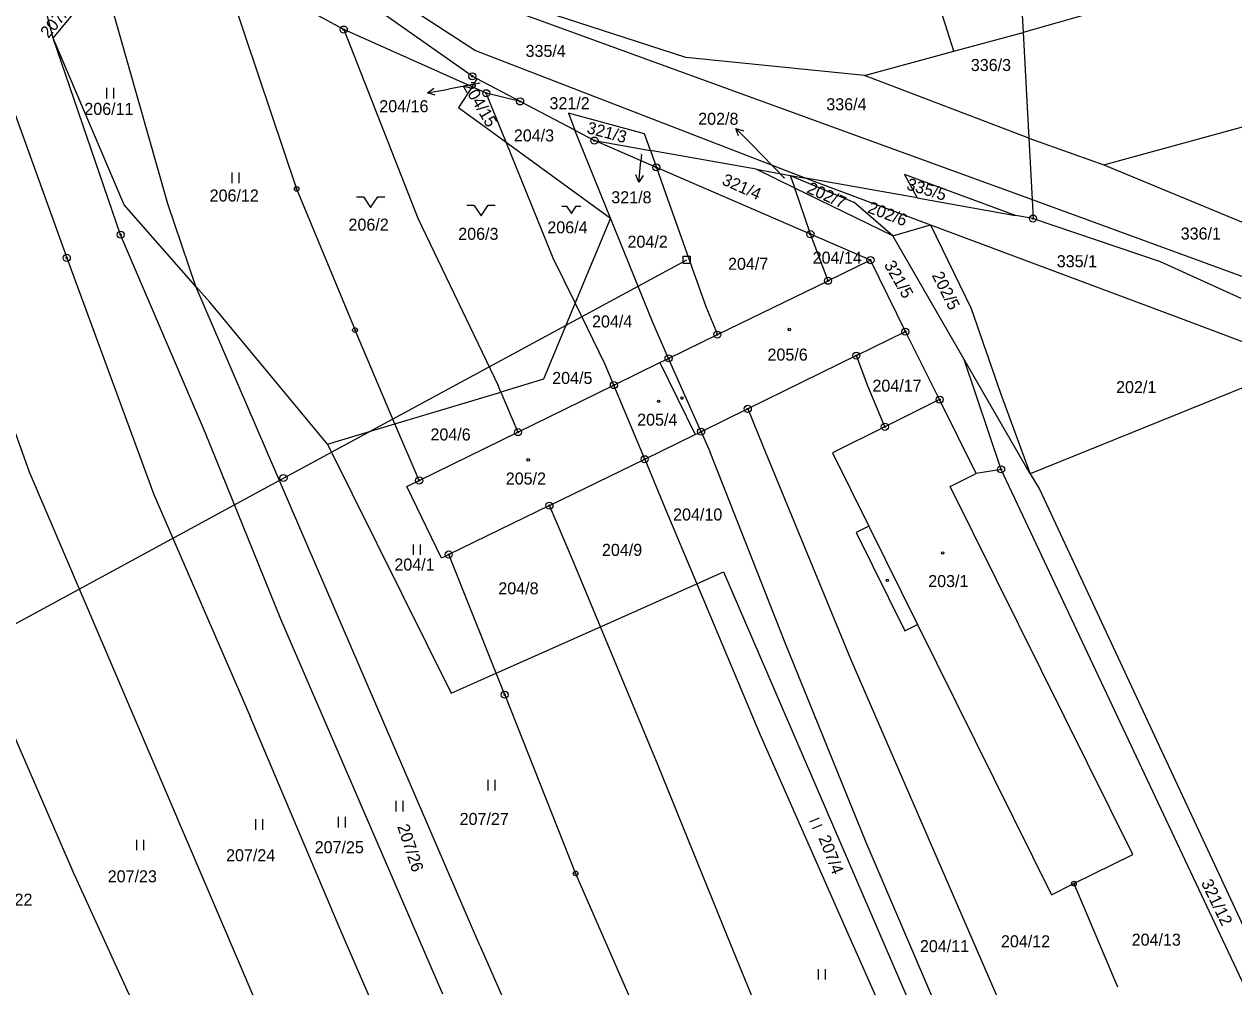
# Model space of a CAD drawing. Extents: x -762263 to -760336, y -1154405 to -1152076.
# Drawn here: x -761293.1 to -761122, y -1152766.2 to -1152630.1 of the extents above; entities that cross this region are included whole.
import ezdxf

# ---------------------------------------------------------------- set-up
doc = ezdxf.new("R2010")
doc.units = 0
for name, color, linetype in [('Vrstva 1', 7, 'Continuous'), ('Vrstva 12', 7, 'Continuous'), ('Vrstva 16', 7, 'Continuous'), ('Vrstva 18', 7, 'Continuous'), ('Vrstva 19', 7, 'Continuous'), ('Vrstva 24', 7, 'Continuous'), ('Vrstva 25', 7, 'Continuous'), ('Vrstva 26', 7, 'Continuous'), ('Vrstva 4', 7, 'Continuous'), ('Vrstva 6', 7, 'Continuous')]:
    doc.layers.add(name, color=color, linetype=linetype)

msp = doc.modelspace()

# ---------------------------------------------------------------- linework, layer by layer
at = {"layer": 'Vrstva 1'}
for p, q in [((-761154.23, -1152586.24), (-761151.83, -1152631.27)), ((-761161.6, -1152633.9), (-761171.9, -1152601.8)), ((-761265.87, -1152610.03), (-761229.28, -1152633.81)), ((-761229.72, -1152637.48), (-761267.05, -1152611.14)), ((-761264.6, -1152623.58), (-761254.56, -1152653.41)), ((-761288.98, -1152632.1), (-761283.69, -1152625.63)), ((-761247.89, -1152630.87), (-761257.04, -1152625.88)), ((-761199.54, -1152634.84), (-761223.07, -1152627.2)), ((-761222.44, -1152628.75), (-761150.56, -1152654.88)), ((-761278.97, -1152655.65), (-761288.98, -1152632.1)), ((-761247.89, -1152630.87), (-761237.42, -1152657.52)), ((-761229.75, -1152638.97), (-761247.89, -1152630.87)), ((-761161.6, -1152633.9), (-761151.83, -1152631.27)), ((-761151.83, -1152631.27), (-761151.03, -1152646.24)), ((-761229.28, -1152633.81), (-761182.55, -1152651.88)), ((-761174.26, -1152637.36), (-761161.6, -1152633.9)), ((-761174.26, -1152637.36), (-761199.54, -1152634.84)), ((-761229.04, -1152637.84), (-761229.72, -1152637.48)), ((-761151.03, -1152646.24), (-761174.26, -1152637.36)), ((-761229.75, -1152638.97), (-761231.68, -1152641.89)), ((-761229.75, -1152638.97), (-761229.04, -1152637.84)), ((-761227.74, -1152639.87), (-761229.75, -1152638.97)), ((-761222.96, -1152641.03), (-761229.04, -1152637.84)), ((-761222.96, -1152641.03), (-761227.74, -1152639.87)), ((-761224.92, -1152646.81), (-761227.74, -1152639.87)), ((-761231.68, -1152641.89), (-761224.92, -1152646.81)), ((-761215.22, -1152645.1), (-761222.96, -1152641.03)), ((-761205.35, -1152645.62), (-761216.1, -1152642.7)), ((-761216.1, -1152642.7), (-761215.22, -1152645.1)), ((-761215.22, -1152645.1), (-761212.44, -1152646.56)), ((-761210.19, -1152657.52), (-761215.22, -1152645.1)), ((-761204.54, -1152647.96), (-761205.35, -1152645.62)), ((-761218.26, -1152663.2), (-761224.92, -1152646.81)), ((-761224.92, -1152646.81), (-761210.19, -1152657.52)), ((-761212.44, -1152646.56), (-761204.54, -1152647.96)), ((-761203.69, -1152650.35), (-761212.44, -1152646.56)), ((-761151.03, -1152646.24), (-761150.56, -1152654.88)), ((-761189.59, -1152650.63), (-761204.54, -1152647.96)), ((-761181.9, -1152659.8), (-761203.69, -1152650.35)), ((-761203.69, -1152650.35), (-761202.4, -1152654)), ((-761184.13, -1152653.28), (-761189.59, -1152650.63)), ((-761189.59, -1152650.63), (-761184.75, -1152651.49)), ((-761184.75, -1152651.49), (-761182.55, -1152651.88)), ((-761166.8, -1152654.68), (-761182.55, -1152651.88)), ((-761182.55, -1152651.88), (-761164.92, -1152658.47)), ((-761152.91, -1152657.15), (-761168.61, -1152651.37)), ((-761168.61, -1152651.37), (-761166.8, -1152654.68)), ((-761254.56, -1152653.41), (-761246.3, -1152673.37)), ((-761202.4, -1152654), (-761196.68, -1152670.04)), ((-761170.25, -1152660.02), (-761184.13, -1152653.28)), ((-761268.8, -1152667.19), (-761278.97, -1152655.65)), ((-761166.8, -1152654.68), (-761152.91, -1152657.15)), ((-761150.56, -1152654.88), (-761150.42, -1152657.59)), ((-761150.56, -1152654.88), (-761087.62, -1152677.96)), ((-761237.42, -1152657.52), (-761226.07, -1152681.21)), ((-761210.19, -1152657.52), (-761215.17, -1152669.5)), ((-761204.21, -1152672.3), (-761210.19, -1152657.52)), ((-761150.42, -1152657.59), (-761152.91, -1152657.15)), ((-761173.41, -1152663.47), (-761181.9, -1152659.8)), ((-761179.41, -1152666.39), (-761181.9, -1152659.8)), ((-761164.92, -1152658.47), (-761128.74, -1152672.01)), ((-761160.15, -1152677.52), (-761170.25, -1152660.02)), ((-761215.17, -1152669.5), (-761218.26, -1152663.2)), ((-761173.41, -1152663.47), (-761179.41, -1152666.39)), ((-761168.48, -1152673.58), (-761173.41, -1152663.47)), ((-761195.06, -1152674), (-761179.41, -1152666.39)), ((-761266.85, -1152669.41), (-761268.8, -1152667.19)), ((-761250.19, -1152689.48), (-761266.85, -1152669.41)), ((-761215.17, -1152669.5), (-761219.67, -1152680.31)), ((-761210.91, -1152678.21), (-761215.17, -1152669.5)), ((-761196.68, -1152670.04), (-761195.06, -1152674)), ((-761240.65, -1152686.61), (-761246.3, -1152673.37)), ((-761201.96, -1152677.36), (-761204.21, -1152672.3)), ((-761128.74, -1152672.01), (-761112.42, -1152678.12)), ((-761201.96, -1152677.36), (-761195.06, -1152674)), ((-761175.41, -1152676.97), (-761168.48, -1152673.58)), ((-761163.63, -1152683.2), (-761168.48, -1152673.58)), ((-761209.69, -1152681.14), (-761210.91, -1152678.21)), ((-761209.69, -1152681.14), (-761203.19, -1152677.96)), ((-761203.19, -1152677.96), (-761201.96, -1152677.36)), ((-761197.36, -1152687.73), (-761201.96, -1152677.36)), ((-761175.41, -1152676.97), (-761190.76, -1152684.5)), ((-761173.83, -1152681.14), (-761175.41, -1152676.97)), ((-761150.81, -1152693.69), (-761160.15, -1152677.52)), ((-761112.42, -1152678.12), (-761150.81, -1152693.69)), ((-761219.67, -1152680.31), (-761225.68, -1152682.12)), ((-761225.68, -1152682.12), (-761226.07, -1152681.21)), ((-761223.26, -1152687.79), (-761209.69, -1152681.14)), ((-761205.34, -1152691.62), (-761209.69, -1152681.14)), ((-761171.38, -1152687.04), (-761173.83, -1152681.14)), ((-761240.65, -1152686.61), (-761225.68, -1152682.12)), ((-761225.68, -1152682.12), (-761223.26, -1152687.79)), ((-761163.63, -1152683.2), (-761171.38, -1152687.04)), ((-761158.46, -1152693.63), (-761163.63, -1152683.2)), ((-761190.76, -1152684.5), (-761197.36, -1152687.73)), ((-761190.76, -1152684.5), (-761188.61, -1152689.74)), ((-761250.19, -1152689.48), (-761240.65, -1152686.61)), ((-761237.23, -1152694.63), (-761240.65, -1152686.61)), ((-761171.38, -1152687.04), (-761178.8, -1152690.72)), ((-761237.23, -1152694.63), (-761223.26, -1152687.79)), ((-761205.34, -1152691.62), (-761198.19, -1152688.14)), ((-761198.19, -1152688.14), (-761197.36, -1152687.73)), ((-761197.36, -1152687.73), (-761196.08, -1152690.62)), ((-761250.19, -1152689.48), (-761232.71, -1152724.72)), ((-761188.61, -1152689.74), (-761176.25, -1152719.87)), ((-761218.81, -1152698.18), (-761205.34, -1152691.62)), ((-761205.34, -1152691.62), (-761202.44, -1152698.58)), ((-761185.49, -1152717.6), (-761196.08, -1152690.62)), ((-761178.8, -1152690.72), (-761173.65, -1152701.1)), ((-761162.14, -1152695.46), (-761158.46, -1152693.63)), ((-761154.94, -1152693.06), (-761158.46, -1152693.63)), ((-761120.45, -1152766.21), (-761154.94, -1152693.06)), ((-761150.81, -1152693.69), (-761149.53, -1152695.84)), ((-761238.97, -1152695.49), (-761237.23, -1152694.63)), ((-761234.07, -1152705.6), (-761238.97, -1152695.49)), ((-761136.32, -1152747.5), (-761162.14, -1152695.46)), ((-761149.53, -1152695.84), (-761118.24, -1152762.89)), ((-761218.81, -1152698.18), (-761233.05, -1152705.1)), ((-761215.55, -1152705.78), (-761218.81, -1152698.18)), ((-761202.44, -1152698.58), (-761197.97, -1152709.24)), ((-761173.65, -1152701.1), (-761175.43, -1152701.98)), ((-761175.43, -1152701.98), (-761168.54, -1152715.9)), ((-761233.05, -1152705.1), (-761234.07, -1152705.6)), ((-761226.34, -1152721.88), (-761233.05, -1152705.1)), ((-761211.59, -1152715.31), (-761215.55, -1152705.78)), ((-761197.97, -1152709.24), (-761194.18, -1152707.55)), ((-761194.18, -1152707.55), (-761166.31, -1152772.15)), ((-761211.59, -1152715.31), (-761197.97, -1152709.24)), ((-761197.97, -1152709.24), (-761189.02, -1152730.61)), ((-761226.34, -1152721.88), (-761211.59, -1152715.31)), ((-761203.45, -1152734.91), (-761211.59, -1152715.31)), ((-761168.54, -1152715.9), (-761166.75, -1152715.01)), ((-761166.75, -1152715.01), (-761147.8, -1152753.21)), ((-761174.02, -1152745.83), (-761185.49, -1152717.6)), ((-761176.25, -1152719.87), (-761135.45, -1152813.8)), ((-761232.71, -1152724.72), (-761226.34, -1152721.88)), ((-761225.13, -1152724.92), (-761226.34, -1152721.88)), ((-761225.13, -1152724.92), (-761215.11, -1152750.19)), ((-761189.02, -1152730.61), (-761176.79, -1152758.28)), ((-761193.62, -1152759.1), (-761203.45, -1152734.91)), ((-761164.38, -1152768.39), (-761174.02, -1152745.83)), ((-761144.64, -1152751.64), (-761136.32, -1152747.5)), ((-761215.11, -1152750.19), (-761179.22, -1152832.52)), ((-761147.8, -1152753.21), (-761144.64, -1152751.64)), ((-761144.64, -1152751.64), (-761138.48, -1152766.24)), ((-761176.79, -1152758.28), (-761164.44, -1152786.14)), ((-761183.54, -1152783.86), (-761193.62, -1152759.1))]:
    msp.add_line(p, q, dxfattribs=at)
at = {"layer": 'Vrstva 12'}
for p, q in [((-761256.42, -1152694.28), (-761199.39, -1152663.43)), ((-761324.27, -1152731.12), (-761256.42, -1152694.28))]:
    msp.add_line(p, q, dxfattribs=at)
at = {"layer": 'Vrstva 16'}
for p, q in [((-761228.64, -1152638.46), (-761233.1, -1152639.28)), ((-761236.05, -1152639.827), (-761233.1, -1152639.28)), ((-761192.431, -1152644.838), (-761190.34, -1152646.99)), ((-761185.59, -1152651.88), (-761190.34, -1152646.99)), ((-761206.164, -1152652.447), (-761205.89, -1152649.46)), ((-761205.8, -1152648.52), (-761205.89, -1152649.46))]:
    msp.add_line(p, q, dxfattribs=at)
for points in [[(-761234.975, -1152640.136), (-761236.05, -1152639.827), (-761235.158, -1152639.153)], [(-761192.092, -1152645.904), (-761192.431, -1152644.838), (-761191.375, -1152645.207)], [(-761205.575, -1152651.497), (-761206.164, -1152652.447), (-761206.571, -1152651.406)]]:
    msp.add_lwpolyline(points, dxfattribs=at)
at = {"layer": 'Vrstva 24'}
for centre, radius in [((-761247.89, -1152630.87), 0.5), ((-761247.89, -1152630.87), 0.1), ((-761229.72, -1152637.48), 0.5), ((-761229.72, -1152637.48), 0.1), ((-761227.74, -1152639.87), 0.5), ((-761227.74, -1152639.87), 0.1), ((-761222.96, -1152641.03), 0.5), ((-761222.96, -1152641.03), 0.1), ((-761212.44, -1152646.56), 0.5), ((-761212.44, -1152646.56), 0.1), ((-761203.69, -1152650.35), 0.5), ((-761203.69, -1152650.35), 0.1), ((-761254.56, -1152653.41), 0.335), ((-761254.56, -1152653.41), 0.067), ((-761150.42, -1152657.59), 0.5), ((-761150.42, -1152657.59), 0.1), ((-761279.45, -1152659.87), 0.5), ((-761279.45, -1152659.87), 0.1), ((-761181.9, -1152659.8), 0.5), ((-761181.9, -1152659.8), 0.1), ((-761287.06, -1152663.15), 0.5), ((-761287.06, -1152663.15), 0.1), ((-761173.41, -1152663.47), 0.5), ((-761173.41, -1152663.47), 0.1), ((-761179.41, -1152666.39), 0.5), ((-761179.41, -1152666.39), 0.1), ((-761246.3, -1152673.37), 0.335), ((-761246.3, -1152673.37), 0.067), ((-761168.48, -1152673.58), 0.5), ((-761168.48, -1152673.58), 0.1), ((-761195.06, -1152674), 0.5), ((-761195.06, -1152674), 0.1), ((-761201.96, -1152677.36), 0.5), ((-761175.41, -1152676.97), 0.5), ((-761175.41, -1152676.97), 0.1), ((-761201.96, -1152677.36), 0.1), ((-761209.69, -1152681.14), 0.5), ((-761209.69, -1152681.14), 0.1), ((-761163.63, -1152683.2), 0.5), ((-761163.63, -1152683.2), 0.1), ((-761190.76, -1152684.5), 0.5), ((-761190.76, -1152684.5), 0.1), ((-761171.38, -1152687.04), 0.5), ((-761171.38, -1152687.04), 0.1), ((-761223.26, -1152687.79), 0.5), ((-761223.26, -1152687.79), 0.1), ((-761197.36, -1152687.73), 0.5), ((-761197.36, -1152687.73), 0.1), ((-761205.34, -1152691.62), 0.5), ((-761205.34, -1152691.62), 0.1), ((-761154.94, -1152693.06), 0.5), ((-761154.94, -1152693.06), 0.1), ((-761237.23, -1152694.63), 0.5), ((-761237.23, -1152694.63), 0.1), ((-761218.81, -1152698.18), 0.5), ((-761218.81, -1152698.18), 0.1), ((-761233.05, -1152705.1), 0.5), ((-761233.05, -1152705.1), 0.1), ((-761225.13, -1152724.92), 0.5), ((-761225.13, -1152724.92), 0.1), ((-761215.11, -1152750.19), 0.335), ((-761215.11, -1152750.19), 0.067), ((-761144.64, -1152751.64), 0.335), ((-761144.64, -1152751.64), 0.067)]:
    msp.add_circle(centre, radius, dxfattribs=at)
at = {"layer": 'Vrstva 25'}
for p, q in [((-761281.42, -1152640.6), (-761281.42, -1152639.1)), ((-761280.42, -1152640.6), (-761280.42, -1152639.1)), ((-761263.67, -1152652.57), (-761263.67, -1152651.07)), ((-761262.67, -1152652.57), (-761262.67, -1152651.07)), ((-761238.05, -1152705.16), (-761238.05, -1152703.66)), ((-761237.05, -1152705.16), (-761237.05, -1152703.66)), ((-761227.48, -1152738.45), (-761227.48, -1152736.95)), ((-761226.48, -1152738.45), (-761226.48, -1152736.95)), ((-761240.49, -1152741.43), (-761240.49, -1152739.93)), ((-761239.49, -1152741.43), (-761239.49, -1152739.93)), ((-761260.35, -1152744.01), (-761260.35, -1152742.51)), ((-761259.35, -1152744.01), (-761259.35, -1152742.51)), ((-761248.66, -1152743.71), (-761248.66, -1152742.21)), ((-761247.66, -1152743.71), (-761247.66, -1152742.21)), ((-761181.995, -1152742.92), (-761180.614, -1152742.335)), ((-761181.605, -1152743.84), (-761180.224, -1152743.255)), ((-761277.15, -1152746.92), (-761277.15, -1152745.42)), ((-761276.15, -1152746.92), (-761276.15, -1152745.42)), ((-761180.75, -1152765.21), (-761180.75, -1152763.71)), ((-761179.75, -1152765.21), (-761179.75, -1152763.71))]:
    msp.add_line(p, q, dxfattribs=at)
for points in [[(-761246.09, -1152654.53), (-761245.09, -1152654.53), (-761244.09, -1152656.03), (-761243.09, -1152654.53), (-761242.09, -1152654.53)], [(-761230.48, -1152655.71), (-761229.48, -1152655.71), (-761228.48, -1152657.21), (-761227.48, -1152655.71), (-761226.48, -1152655.71)], [(-761217.05, -1152655.855), (-761216.38, -1152655.855), (-761215.71, -1152656.86), (-761215.04, -1152655.855), (-761214.37, -1152655.855)]]:
    msp.add_lwpolyline(points, dxfattribs=at)
for centre in [(-761184.89, -1152673.28), (-761203.37, -1152683.44), (-761200.06, -1152682.98), (-761221.81, -1152691.71), (-761163.21, -1152704.87), (-761171.04, -1152708.74)]:
    msp.add_circle(centre, 0.175, dxfattribs=at)
at = {"layer": 'Vrstva 26'}
msp.add_lwpolyline([(-761199.89, -1152662.93), (-761198.89, -1152662.93), (-761198.89, -1152663.93), (-761199.89, -1152663.93)], close=True, dxfattribs=at)
msp.add_circle((-761256.42, -1152694.28), 0.5, dxfattribs=at)
at = {"layer": 'Vrstva 4'}
for p, q in [((-761203.19, -1152677.96), (-761198.19, -1152688.14)), ((-761173.65, -1152701.1), (-761166.75, -1152715.01))]:
    msp.add_line(p, q, dxfattribs=at)
at = {"layer": 'Vrstva 6'}
for p, q in [((-761140.4, -1152649.98), (-761010.32, -1152614.36)), ((-761272.76, -1152655.53), (-761281.36, -1152625.21)), ((-761288.98, -1152632.1), (-761290.35, -1152626.84)), ((-761299.47, -1152628.81), (-761287.06, -1152663.15)), ((-761142.2, -1152628.53), (-761151.83, -1152631.27)), ((-761292.33, -1152693.43), (-761314.49, -1152631.78)), ((-761279.45, -1152659.87), (-761288.98, -1152632.1)), ((-761151.03, -1152646.24), (-761140.4, -1152649.98)), ((-761204.54, -1152647.96), (-761203.69, -1152650.35)), ((-761140.4, -1152649.98), (-761109.42, -1152662.87)), ((-761184.75, -1152651.49), (-761175.75, -1152655.27)), ((-761184.75, -1152651.49), (-761184.13, -1152653.28)), ((-761181.9, -1152659.8), (-761184.13, -1152653.28)), ((-761268.8, -1152667.19), (-761272.76, -1152655.53)), ((-761170.25, -1152660.02), (-761175.75, -1152655.27)), ((-761150.42, -1152657.59), (-761132.45, -1152663.66)), ((-761170.25, -1152660.02), (-761164.92, -1152658.47)), ((-761164.92, -1152658.47), (-761159.19, -1152670.29)), ((-761267.44, -1152687.93), (-761279.45, -1152659.87)), ((-761287.06, -1152663.15), (-761274.73, -1152696.61)), ((-761132.45, -1152663.66), (-761121.06, -1152668.84)), ((-761228.66, -1152760.37), (-761268.8, -1152667.19)), ((-761159.19, -1152670.29), (-761155.04, -1152682.27)), ((-761154.94, -1152693.06), (-761160.15, -1152677.52)), ((-761155.04, -1152682.27), (-761150.81, -1152693.69)), ((-761256.77, -1152714.23), (-761267.44, -1152687.93)), ((-761311.86, -1152690.78), (-761286.2, -1152749.91)), ((-761260.42, -1152768.1), (-761292.33, -1152693.43)), ((-761274.73, -1152696.61), (-761261.14, -1152728.02)), ((-761233.9, -1152767.28), (-761256.77, -1152714.23)), ((-761248.31, -1152758.32), (-761261.14, -1152728.02)), ((-761286.2, -1152749.91), (-761252.11, -1152824.66)), ((-761228.79, -1152802.98), (-761248.31, -1152758.32)), ((-761228.66, -1152760.37), (-761200.52, -1152824.24))]:
    msp.add_line(p, q, dxfattribs=at)

# ---------------------------------------------------------------- texts
at = {"layer": 'Vrstva 16'}
for s, p in [('204/16', (-761242.868, -1152642.55)), ('202/8', (-761197.773, -1152644.33)), ('321/8', (-761210.06, -1152655.43))]:
    msp.add_text(s, height=1.7, dxfattribs=at).set_placement(p)
at = {"layer": 'Vrstva 18'}
for s, rotation, p in [('207/28', 50.1911, (-761289.658, -1152632.195)), ('204/15', 300.63096, (-761231.108, -1152638.856)), ('321/3', 345.26437, (-761213.64, -1152645.49)), ('321/4', 336.15434, (-761194.549, -1152652.718)), ('202/7', 335.75327, (-761182.532, -1152653.885)), ('335/5', 343.08713, (-761168.421, -1152653.443)), ('202/6', 339.13372, (-761173.941, -1152656.695)), ('321/5', 299.82881, (-761171.548, -1152664.124)), ('202/5', 296.84943, (-761164.76, -1152665.61)), ('207/26', 288.42695, (-761240.355, -1152743.542)), ('207/4', 291.34904, (-761180.802, -1152745.176)), ('321/12', 295.87541, (-761126.708, -1152751.506))]:
    msp.add_text(s, height=1.7, rotation=rotation, dxfattribs=at).set_placement(p)
for s, height, p in [('335/4', 1.7, (-761222.183, -1152634.74)), ('336/3', 1.7, (-761159.223, -1152636.73)), ('204/16', 0.1, (-761228.868, -1152638.46)), ('321/2', 1.7, (-761218.803, -1152642.13)), ('336/4', 1.7, (-761179.653, -1152642.28)), ('206/11', 1.7, (-761284.577, -1152642.93)), ('204/3', 1.7, (-761223.841, -1152646.69)), ('321/8', 0.1, (-761205.992, -1152648.52)), ('202/8', 0.1, (-761185.803, -1152651.88)), ('206/12', 1.7, (-761266.858, -1152655.18)), ('206/2', 1.7, (-761247.223, -1152659.3)), ('206/4', 1.7, (-761219.104, -1152659.68)), ('206/3', 1.7, (-761231.703, -1152660.6)), ('336/1', 1.7, (-761129.539, -1152660.56)), ('204/2', 1.7, (-761207.767, -1152661.71)), ('204/7', 1.7, (-761193.553, -1152664.84)), ('204/14', 1.7, (-761181.585, -1152663.97)), ('335/1', 1.7, (-761147.066, -1152664.47)), ('204/4', 1.7, (-761212.784, -1152672.99)), ('204/5', 1.7, (-761218.42, -1152680.98)), ('204/17', 1.7, (-761173.135, -1152682.07)), ('202/1', 1.7, (-761138.679, -1152682.27)), ('204/6', 1.7, (-761235.634, -1152688.97)), ('204/10', 1.7, (-761201.322, -1152700.29)), ('204/9', 1.7, (-761211.384, -1152705.29)), ('204/1', 1.7, (-761240.736, -1152707.36)), ('204/8', 1.7, (-761226.034, -1152710.73)), ('207/27', 1.7, (-761231.506, -1152743.34)), ('207/24', 1.7, (-761264.536, -1152748.47)), ('207/25', 1.7, (-761252.003, -1152747.33)), ('207/23', 1.7, (-761281.273, -1152751.45)), ('207/22', 1.7, (-761298.87, -1152754.75)), ('204/12', 1.7, (-761154.958, -1152760.64)), ('204/13', 1.7, (-761136.472, -1152760.41)), ('204/11', 1.7, (-761166.417, -1152761.32))]:
    msp.add_text(s, height=height, dxfattribs=at).set_placement(p)
at = {"layer": 'Vrstva 19'}
for s, p in [('205/6', (-761187.973, -1152677.68)), ('205/4', (-761206.403, -1152686.88)), ('205/2', (-761224.983, -1152695.2)), ('203/1', (-761165.243, -1152709.7))]:
    msp.add_text(s, height=1.7, dxfattribs=at).set_placement(p)

doc.saveas('drawing.dxf')
